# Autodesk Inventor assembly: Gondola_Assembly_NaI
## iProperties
Shininess: 64.0
Length Units: 11272
Angle Units: 11279
Time Units: 11290
Mass Units: 11286
Length Display Precision: 3
Angle Display Precision: 2
Compacted: True
Part Number: Gondola_Assembly_NaI
Document SubType Name: Assembly
Created: 2004-08
Designer: John Blackburn
Manufacturer: Standard
Standards Organization: Custom
Density: 0.0
Volumn: 0.0
Area: 0.0
PropertySet Name: Model Information
Control State: 0
Master: False
Checked Out: False
Author: John Blackburn
